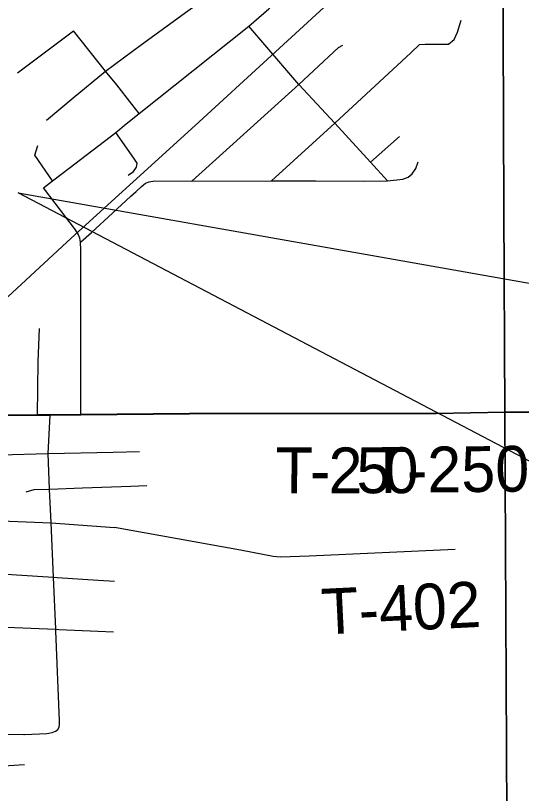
# Model space of a CAD drawing. Extents: x 0 to 34, y 0 to 22.
# Drawn here: x 5.679 to 6.308, y 16.545 to 17.511 of the extents above; entities that cross this region are included whole.
import ezdxf

# ---------------------------------------------------------------- set-up
doc = ezdxf.new("R2010")
doc.units = 0
for name, color, linetype in [('Default', 7, 'Continuous'), ('SH_Cut_Line', 7, 'Continuous'), ('SH_Text', 7, 'Continuous')]:
    doc.layers.add(name, color=color, linetype=linetype)

msp = doc.modelspace()

# ---------------------------------------------------------------- linework, layer by layer
at = {"layer": 'Default'}
for p, q in [((5.68146, 17.44042), (5.75113, 17.49239)), ((6.12009, 17.32924), (6.15609, 17.36133)), ((5.99179, 17.01675), (5.89538, 17.01672))]:
    msp.add_line(p, q, dxfattribs=at)
for points in [[(8.9, 20.9), (6.23149, 20.9), (6.24319, 19.89371), (6.27052, 18.50117), (6.27659, 18.30213), (6.28184, 17.78925), (6.284, 17.78473), (6.28515, 17.78124), (6.28571, 17.77661), (6.28515, 17.77001), (6.28473, 17.76733), (6.28374, 17.76089), (6.28289, 17.74896), (6.28276, 17.73875), (6.28328, 17.73003), (6.28371, 17.72768), (6.28415, 17.72533), (6.28432, 17.72097), (6.28432, 17.7119), (6.2861, 17.27145), (6.28712, 17.01877), (6.32154, 17.01891)], [(5.71737, 17.38161), (5.75063, 17.40923), (5.79099, 17.44226), (5.83553, 17.47545), (5.89321, 17.51717), (5.9264, 17.54119), (5.95392, 17.56232), (5.97339, 17.57896), (6.00338, 17.6071), (6.02427, 17.62696), (6.07408, 17.67364), (6.10794, 17.70748), (6.13308, 17.73077), (6.18038, 17.7762), (6.20226, 17.79487)], [(5.50582, 17.01113), (5.74827, 17.23511), (5.90211, 17.37498), (6.09202, 17.54914), (6.27777, 17.71906)], [(5.64821, 17.01509), (5.70601, 17.0155), (5.72207, 17.01562), (5.76015, 17.01611), (5.89518, 17.01727), (6.20175, 17.01737), (6.28712, 17.01877), (6.2861, 17.27145), (6.28432, 17.7119)], [(5.81659, 17.37681), (5.83275, 17.38989), (5.96909, 17.49821), (5.99393, 17.51975), (6.02043, 17.54423), (6.04273, 17.56541), (6.14918, 17.66472), (6.19862, 17.71128)], [(5.81659, 17.37681), (5.83275, 17.38989), (5.96909, 17.49821), (5.99393, 17.51975), (6.02043, 17.54423), (6.04273, 17.56541), (6.14918, 17.66472), (6.19862, 17.71128)], [(5.9972, 17.30605), (6.07602, 17.37784), (6.17035, 17.46489), (6.18123, 17.47526), (6.18804, 17.47598), (6.20392, 17.47604), (6.21727, 17.47591), (6.22414, 17.48174), (6.22841, 17.49095), (6.23308, 17.50559)], [(6.14151, 17.30602), (6.12009, 17.32924), (6.07602, 17.37784), (6.03112, 17.42589), (5.96909, 17.49821)], [(5.83275, 17.38989), (5.82374, 17.40134), (5.80487, 17.4254), (5.79099, 17.44226), (5.75113, 17.49239)], [(5.89824, 17.30561), (6.03112, 17.42589), (6.08026, 17.47151), (6.08571, 17.47449)], [(5.74558, 17.3218), (5.80351, 17.36621), (5.81659, 17.37681)], [(5.74558, 17.3218), (5.80351, 17.36621), (5.81659, 17.37681)], [(5.81896, 17.31334), (5.82583, 17.31788), (5.82959, 17.32293), (5.83023, 17.32812), (5.82622, 17.33434), (5.80351, 17.36621)], [(5.72495, 17.30599), (5.70302, 17.3379), (5.70665, 17.34983)], [(5.7137, 17.29724), (5.7137, 17.29724), (5.72495, 17.30599), (5.74558, 17.3218)], [(5.7137, 17.29724), (5.72495, 17.30599), (5.74558, 17.3218)], [(5.75984, 17.23009), (5.77354, 17.24195), (5.79953, 17.26613), (5.82222, 17.28709), (5.82907, 17.29277), (5.83576, 17.29912), (5.84042, 17.30333), (5.84522, 17.30501), (5.85157, 17.30599), (5.89824, 17.30561), (5.9972, 17.30605), (6.05215, 17.30592), (6.11216, 17.3056), (6.14151, 17.30602), (6.16025, 17.30799), (6.16719, 17.31065), (6.17218, 17.3148), (6.17645, 17.32141), (6.17957, 17.32983)], [(5.76035, 17.01556), (5.76019, 17.22039), (5.75984, 17.23009), (5.75903, 17.23484), (5.75676, 17.23996), (5.75339, 17.24534), (5.72847, 17.27834), (5.7137, 17.29724)], [(5.70621, 17.01495), (5.70703, 17.08133), (5.70865, 17.12261)], [(5.57783, 17.01363), (5.64841, 17.01454), (5.70621, 17.01495), (5.72227, 17.01507), (5.76035, 17.01556), (5.89538, 17.01672)], [(6.29221, 16.01522), (6.28712, 17.01877), (6.20175, 17.01737), (5.89518, 17.01727), (5.76015, 17.01611), (5.72207, 17.01562), (5.70601, 17.0155), (5.64821, 17.01509)], [(5.72824, 16.62229), (5.73149, 16.62487), (5.73324, 16.62757), (5.73388, 16.63155), (5.73381, 16.63565), (5.72901, 16.74736), (5.72893, 16.74913), (5.72614, 16.81397), (5.72324, 16.88148), (5.72144, 16.92339), (5.71954, 16.9674), (5.72227, 17.01507)], [(6.28732, 17.01822), (6.20195, 17.01683), (5.9986, 17.01676), (5.99179, 17.01675)], [(6.33339, 17.01807), (6.32174, 17.01836), (6.28732, 17.01822)], [(5.62086, 16.94784), (5.64588, 16.96092), (5.65118, 16.96325), (5.66028, 16.96601), (5.71954, 16.9674), (5.80059, 16.9693), (5.83297, 16.97007)], [(5.69235, 16.91996), (5.70221, 16.92272), (5.72144, 16.92339), (5.7622, 16.9248), (5.82218, 16.92689), (5.84218, 16.92759)], [(5.661, 16.88397), (5.72324, 16.88148), (5.77388, 16.87758), (5.80202, 16.87542)], [(6.22535, 16.84816), (6.04382, 16.83985), (6.00839, 16.83857), (5.99941, 16.83939), (5.95844, 16.84734), (5.80202, 16.87542)], [(5.64968, 16.81898), (5.68015, 16.81698), (5.72614, 16.81397), (5.73093, 16.81365), (5.78171, 16.81032), (5.80202, 16.80899)], [(5.63615, 16.75319), (5.72893, 16.74913), (5.73303, 16.74895), (5.78148, 16.74683), (5.80085, 16.74598)], [(5.72824, 16.62229), (5.72417, 16.62073), (5.72051, 16.61994), (5.718, 16.61952), (5.69024, 16.6181), (5.68926, 16.61811), (5.63044, 16.61853)], [(5.60149, 16.57503), (5.6508, 16.57847), (5.67053, 16.57984), (5.69025, 16.58122)]]:
    msp.add_lwpolyline(points, dxfattribs=at)
msp.add_lwpolyline([(6.28922, 14.1), (8.9, 14.1), (8.9, 17.02001), (8.20086, 17.01962), (7.21095, 17.01907), (7.20449, 17.01906), (6.93281, 17.01892), (6.92701, 17.01892), (6.69035, 17.01435), (6.38757, 17.01726), (6.32154, 17.01891), (6.28712, 17.01877), (6.29221, 16.01522), (6.29589, 15.27055), (6.29257, 14.89719), (6.28894, 14.49057), (6.28917, 14.18001)], close=True, dxfattribs=at)
at = {"layer": 'SH_Cut_Line'}
for points in [[(8.9, 20.9), (6.23149, 20.9), (6.24319, 19.89371), (6.27052, 18.50117), (6.27659, 18.30213), (6.28184, 17.78925), (6.284, 17.78473), (6.28515, 17.78124), (6.28571, 17.77661), (6.28515, 17.77001), (6.28473, 17.76733), (6.28374, 17.76089), (6.28289, 17.74896), (6.28276, 17.73875), (6.28328, 17.73003), (6.28371, 17.72768), (6.28415, 17.72533), (6.28432, 17.72097), (6.28432, 17.7119), (6.2861, 17.27145), (6.28712, 17.01877), (6.32154, 17.01891)], [(5.64821, 17.01509), (5.70601, 17.0155), (5.72207, 17.01562), (5.76015, 17.01611), (5.89518, 17.01727), (6.20175, 17.01737), (6.28712, 17.01877), (6.2861, 17.27145), (6.28432, 17.7119)], [(6.32154, 17.01891), (6.28712, 17.01877), (6.20175, 17.01737), (5.89518, 17.01727), (5.76015, 17.01611), (5.72207, 17.01562), (5.70601, 17.0155), (5.64821, 17.01509)]]:
    msp.add_lwpolyline(points, dxfattribs=at)
at = {"layer": 'SH_Text'}
msp.add_lwpolyline([(5.68217, 17.29102), (7.40733, 16.98673), (7.40733, 16.38673)], close=True, dxfattribs=at)

# ---------------------------------------------------------------- texts
at = {"layer": 'Default'}
for s, height, rotation, p in [('T', 0.05682, 359.79108, (6.00228, 16.9183)), ('2', 0.05682, 0.00836, (6.06806, 16.91813)), ('5', 0.05682, 0.08279, (6.10286, 16.91814)), ('T-250', 0.056818, 0.56141, (6.11931, 16.91839)), ('0', 0.05682, 0.1176, (6.13762, 16.91819)), ('-', 0.05682, 359.97373, (6.0449, 16.91814)), ('T-402', 0.056818, 2.80592, (6.06041, 16.74253))]:
    msp.add_text(s, height=height, rotation=rotation, dxfattribs=at).set_placement(p)

doc.saveas('drawing.dxf')
